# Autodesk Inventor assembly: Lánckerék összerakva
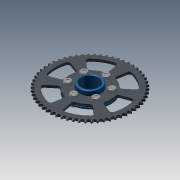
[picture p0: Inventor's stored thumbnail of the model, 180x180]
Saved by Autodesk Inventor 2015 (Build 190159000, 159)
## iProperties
Created: 2013-02
Part Number: Lánckerék összerakva
Document SubType Name: Assembly
Designer: Marci
Author: Marci
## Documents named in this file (5)
- C:\Users\Andrew Almeida\Documents\Projeto WS2015\WS2015 CAD Data ANLAS\01\Pneumatic System\Engine\Pneumatikus hajtás\Lánckerék összerakva.iam
- C:\Users\Andrew Almeida\Documents\Projeto WS2015\WS2015 CAD Data ANLAS\01\Pneumatic System\Engine\Pneumatikus hajtás\Lánckerékagy.ipt
- C:\Users\Andrew Almeida\Documents\Projeto WS2015\WS2015 CAD Data ANLAS\01\Pneumatic System\Engine\Pneumatikus hajtás\Lánc\Design Accelerator\Roller Chain Sprocket11.ipt
- C:\Users\Andrew Almeida\Documents\Projeto WS2015\WS2015 CAD Data ANLAS\01\Pneumatic System\Engine\Pneumatikus hajtás\ISO 4017 - M8 x 16ISO.ipt
- C:\Users\Andrew Almeida\Documents\Projeto WS2015\WS2015 CAD Data ANLAS\01\Pneumatic System\Engine\Pneumatikus hajtás\ISO 4032 - M8ISO.ipt
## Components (14 placed, 4 different names)
1. Lánckerékagy:1 — Mate:1, Mate:2, Mate:3
2. Roller Chain Sprocket1:1 — Mate:1, Mate:2, Mate:3
3. ISO 4017 - M8 x 16ISO:1
4. ISO 4017 - M8 x 16ISO:2
5. ISO 4017 - M8 x 16ISO:3
6. ISO 4017 - M8 x 16ISO:4
7. ISO 4017 - M8 x 16ISO:5
8. ISO 4017 - M8 x 16ISO:6
9. ISO 4032 - M8ISO:1
10. ISO 4032 - M8ISO:2
11. ISO 4032 - M8ISO:3
12. ISO 4032 - M8ISO:4
13. ISO 4032 - M8ISO:5
14. ISO 4032 - M8ISO:6
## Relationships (3: Mate 3)
- Mate:1: Lánckerékagy:1 ↔ Roller Chain Sprocket1:1
- Mate:2: Lánckerékagy:1 ↔ Roller Chain Sprocket1:1
- Mate:3: Lánckerékagy:1 ↔ Roller Chain Sprocket1:1
